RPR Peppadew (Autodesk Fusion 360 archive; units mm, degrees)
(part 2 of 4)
extrude "Extrude135" cut of existing geometry blind -3
extrude "Extrude136" cut of existing geometry blind -3
extrude "Extrude137" add of existing geometry blind 14
sketch "Sketch111" plane through (0, 0, 5) normal (0, 0, 1) x axis (1, 0, 0)
  line L1 (18.7, -99.4015) -> (49, -99.4015)
  line L2 (18.7, -90.8015) -> (18.7, -99.4015)
  line L3 (9, -90.8015) -> (18.7, -90.8015)
  line L4 (6.05, -90.8015) -> (9, -90.8015)
  line L5 (6.05, -100.6015) -> (6.05, -90.8015)
  line L6 (3, -100.6015) -> (6.05, -100.6015)
  line L7 (3, -101.4015) -> (3, -100.6015)
  line L8 (49, -101.4015) -> (3, -101.4015)
  line L9 (49, -99.4015) -> (49, -101.4015)
extrude "Extrude7" cut sketch "Sketch111" along normal blind 14
extrude "Extrude138" add of existing geometry blind 14
sketch "Sketch112" plane through (0, 0, 19) normal (0, 0, 1) x axis (1, 0, 0)
  line L1 (18.7, -99.4015) -> (49, -99.4015)
  line L2 (18.7, -90.8015) -> (18.7, -99.4015)
  line L3 (6.05, -90.8015) -> (18.7, -90.8015)
  line L4 (6.05, -100.6015) -> (6.05, -90.8015)
  line L5 (3, -100.6015) -> (6.05, -100.6015)
  line L6 (3, -101.4015) -> (3, -100.6015)
  line L7 (49, -101.4015) -> (3, -101.4015)
  line L8 (49, -99.4015) -> (49, -101.4015)
  line L9 (6.7, -33.0015) -> (6.7, -39.8015)
  line L10 (-9, -33.0015) -> (6.7, -33.0015)
  line L11 (-9, -12.8015) -> (-9, -33.0015)
  line L12 (-6.05, -12.8015) -> (-9, -12.8015)
  line L13 (-6.05, -3.0015) -> (-6.05, -12.8015)
  line L14 (-3, -3.0015) -> (-6.05, -3.0015)
  line L15 (-3, -2.2015) -> (-3, -3.0015)
  line L16 (-13.7, -2.2015) -> (-3, -2.2015)
  line L17 (-13.7, -39.8015) -> (-13.7, -2.2015)
  line L18 (6.7, -39.8015) -> (-13.7, -39.8015)
  line L19 (9, -4.2015) -> (9, -12.8015)
  line L20 (49, -4.2015) -> (9, -4.2015)
  line L21 (49, -2.2015) -> (49, -4.2015)
  line L22 (3, -2.2015) -> (49, -2.2015)
  line L23 (3, -3.0015) -> (3, -2.2015)
  line L24 (6.05, -3.0015) -> (3, -3.0015)
  line L25 (6.05, -12.8015) -> (6.05, -3.0015)
  line L26 (9, -12.8015) -> (6.05, -12.8015)
  line L27 (-6.05, -3.0015) -> (6.05, -3.0015)
  line L28 (-6.05, -2.2015) -> (-6.05, -3.0015)
  line L29 (6.05, -2.2015) -> (-6.05, -2.2015)
  line L30 (6.05, -3.0015) -> (6.05, -2.2015)
  line L31 (-13.7, -101.4015) -> (-13.7, -73.6015)
  line L32 (-3, -101.4015) -> (-13.7, -101.4015)
  line L33 (-3, -100.6015) -> (-3, -101.4015)
  line L34 (-6.05, -100.6015) -> (-3, -100.6015)
  line L35 (-6.05, -90.8015) -> (-6.05, -100.6015)
  line L36 (-9, -90.8015) -> (-6.05, -90.8015)
  line L37 (-9, -73.6015) -> (-9, -90.8015)
  line L38 (-13.7, -73.6015) -> (-9, -73.6015)
  line L39 (6.05, -100.6015) -> (-6.05, -100.6015)
  line L40 (6.05, -101.4015) -> (6.05, -100.6015)
  line L41 (-6.05, -101.4015) -> (6.05, -101.4015)
  line L42 (-6.05, -100.6015) -> (-6.05, -101.4015)
  point P30 (-6.05, -2.2015)
  point P26 (6.05, -3.0015)
  point P28 (6.05, -3.0015)
  point P42 (6.05, -101.4015)
  point P36 (-6.05, -100.6015)
  point P40 (-6.05, -100.6015)
  horizontal L27
  vertical L28
  horizontal L29
  vertical L30
  coincident L16 P30
  coincident P26 P28
  horizontal L39
  vertical L40
  horizontal L41
  vertical L42
  coincident L7 P42
  coincident P36 P40
extrude "Extrude139" cut sketch "Sketch112" profile of L5 L6 L7 L14 L15 L16 L22 L23 L24 L27 L28 L29 L30 L32 L33 L34 L39 L40 L41 L42 against normal blind 14.05
chamfer "Chamfer9" distance 8
sketch "Sketch113" plane through (0, -2.2015, 0) normal (0, 1, 0) x axis (-1, 0, 0)
  line L1 (13.7, -5) -> (5.7, -13)
  line L2 (13.7, 19) -> (13.7, -5)
  line L3 (6.05, 19) -> (13.7, 19)
  line L4 (6.05, 4.95) -> (6.05, 19)
  line L5 (3, 4.95) -> (6.05, 4.95)
  line L6 (3, 0) -> (3, 4.95)
  line L7 (-3, 4.95) -> (-3, 0)
  line L8 (-6.05, 4.95) -> (-3, 4.95)
  line L9 (-6.05, 19) -> (-6.05, 4.95)
  line L10 (-49, 19) -> (-6.05, 19)
  line L11 (-49, -13) -> (-49, 19)
  line L12 (5.7, -13) -> (-49, -13)
  line L13 (-106.3, -13) -> (13.7, 19)
  line L14 (8.7, -13) -> (-21.65, -13)
  line L15 (-106.3, -13) -> (8.7, -13)
  line L16 (-106.3, 70) -> (-106.3, -13)
  line L17 (13.7, 70) -> (-106.3, 70)
  line L18 (13.7, 19) -> (13.7, 70)
  arc A1 centre (0, 0) radius 3 clockwise from (3, 0) to (-3, 0)
  point P4 (13.7, 19)
  point P16 (13.7, 19)
  point P17 (-21.65, -13)
  point P18 (8.7, -13)
  point P19 (-106.3, -13)
  coincident P4 P16
  midpoint L12 P17
  coincident L12 P18
  parallel L12 L14
  parallel L12 L15
  perpendicular L15 L16
  perpendicular L2 L17
  perpendicular L3 L18
  dimension "d696" distance L2 P19 = 120
extrude "Extrude140" add of existing geometry blind 20
extrude "Extrude141" cut sketch "Sketch113" profile of L3 L4 L9 L10 L11 L13 L16 L17 L18 against normal blind 30.8
sketch "Sketch114" plane through (0, -101.4015, 0) normal (0, -1, 0) x axis (1, 0, 0)
  line L1 (-5.7, -13) -> (-13.7, -5)
  line L2 (69, -13) -> (-5.7, -13)
  line L3 (69, 19) -> (69, -13)
  line L4 (6.05, 19) -> (69, 19)
  line L5 (6.05, 4.95) -> (6.05, 19)
  line L6 (3, 4.95) -> (6.05, 4.95)
  line L7 (3, 0) -> (3, 4.95)
  line L8 (-3, 4.95) -> (-3, 0)
  line L9 (-6.05, 4.95) -> (-3, 4.95)
  line L10 (-6.05, 19) -> (-6.05, 4.95)
  line L11 (-13.7, 19) -> (-6.05, 19)
  line L12 (-13.7, -5) -> (-13.7, 19)
  line L13 (69, -3.0533) -> (6.05, 13.7333)
  line L14 (69, -13) -> (69, -3.0533)
  line L15 (-5.7, -13) -> (69, -13)
  line L16 (-13.7, -5) -> (-5.7, -13)
  line L17 (-13.7, 19) -> (-13.7, -5)
  line L18 (-6.05, 16.96) -> (-13.7, 19)
  line L19 (-6.05, 4.95) -> (-6.05, 16.96)
  line L20 (-3, 4.95) -> (-6.05, 4.95)
  line L21 (-3, 0) -> (-3, 4.95)
  line L22 (3, 4.95) -> (3, 0)
  line L23 (6.05, 4.95) -> (3, 4.95)
  line L24 (6.05, 13.7333) -> (6.05, 4.95)
  arc A1 centre (0, 0) radius 3 clockwise from (3, 0) to (-3, 0)
  arc A2 centre (0, 0) radius 3 clockwise from (3, 0) to (-3, 0)
extrude "Extrude142" cut sketch "Sketch114" profile of L3 L4 L5 L10 L11 L13 L18 against normal blind 10.6
component_insert "Component Insert8"
as_built_joint "As-built7"
joint "Assemble6" alignAngle 0 alignOffsetX -7 alignOffsetY 50 alignOffsetZ 0
extrude "Extrude143" add of existing geometry blind 3
sketch "Sketch115" plane through (0, -33.0015, 0) normal (0, 1, 0) x axis (-1, 0, 0)
  line L1 (-14.2, -11) -> (-14.2, 11.5)
  line L2 (-9, -11) -> (-14.2, -11)
  line L3 (-9, -2.3714) -> (-9, -11)
  line L4 (-6.9285, -2.3714) -> (-9, -2.3714)
  line L5 (-5.6202, -2.3714) -> (-6.9285, -2.3714)
  line L6 (3, -5.1) -> (-3, -5.1)
  line L7 (6.9285, -2.3714) -> (5.6202, -2.3714)
  line L8 (9, -2.3714) -> (6.9285, -2.3714)
  line L9 (9, 17.7467) -> (9, -2.3714)
  line L10 (13.7, 19) -> (9, 17.7467)
  line L11 (-6.7, 19) -> (13.7, 19)
  line L12 (-69, -3.0533) -> (-6.05, 13.7333)
  line L13 (-69, -13) -> (-69, -3.0533)
  line L14 (5.7, -13) -> (-69, -13)
  line L15 (13.7, -5) -> (5.7, -13)
  line L16 (13.7, 19) -> (13.7, -5)
  line L17 (6.05, 16.96) -> (13.7, 19)
  line L18 (6.05, 4.95) -> (6.05, 16.96)
  line L19 (3, 4.95) -> (6.05, 4.95)
  line L20 (3, 0) -> (3, 4.95)
  line L21 (-3, 4.95) -> (-3, 0)
  line L22 (-6.05, 4.95) -> (-3, 4.95)
  line L23 (-6.05, 13.7333) -> (-6.05, 4.95)
  line L24 (-69, -11.0004) -> (-9, -11.0004)
  line L25 (-9, -11.0004) -> (-69, -11.0004)
  arc A1 centre (0, 0) radius 6.1 clockwise from (-3.66, -4.88) to (-5.6202, -2.3714)
  arc A2 centre (-3, -4) radius 1.1 clockwise from (-3, -5.1) to (-3.66, -4.88)
  arc A3 centre (3, -4) radius 1.1 clockwise from (3.66, -4.88) to (3, -5.1)
  arc A4 centre (0, 0) radius 6.1 clockwise from (5.6202, -2.3714) to (3.66, -4.88)
  arc A5 centre (-6.7, 11.5) radius 7.5 clockwise from (-14.2, 11.5) to (-6.7, 19)
  circle C1 centre (-7.95, 12.8) radius 1.25
  arc A6 centre (0, 0) radius 3 clockwise from (3, 0) to (-3, 0)
extrude "Extrude144" add sketch "Sketch115" profile of L1 L2 L3 L4 L5 A1 A2 L6 A3 A4 L7 L8 L9 L10 L12 L13 L14 L15 L16 L17 against normal blind 5
sketch "Sketch116" plane through (0, -33.0015, 0) normal (0, 1, 0) x axis (-1, 0, 0)
  line L1 (-69, -3.0533) -> (-14.1998, 11.5601)
  line L2 (-69, -11.0004) -> (-69, -3.0533)
  line L3 (-9, -11.0004) -> (-69, -11.0004)
  line L4 (-9, -2.3714) -> (-9, -11.0004)
  line L5 (-6.9285, -2.3714) -> (-9, -2.3714)
  line L6 (-5.6202, -2.3714) -> (-6.9285, -2.3714)
  line L7 (3, -5.1) -> (-3, -5.1)
  line L8 (6.9285, -2.3714) -> (5.6202, -2.3714)
  line L9 (9, -2.3714) -> (6.9285, -2.3714)
  line L10 (9, 17.7467) -> (9, -2.3714)
  line L11 (13.7, 19) -> (9, 17.7467)
  line L12 (-6.7, 19) -> (13.7, 19)
  line L13 (-20.1998, -11.0004) -> (-69, -11.0004)
  line L14 (-20.1998, 9.9601) -> (-20.1998, -11.0004)
  line L15 (-69, 9.9601) -> (-20.1998, 9.9601)
  line L16 (-69, -11.0004) -> (-69, 9.9601)
  arc A1 centre (0, 0) radius 6.1 clockwise from (-3.66, -4.88) to (-5.6202, -2.3714)
  arc A2 centre (-3, -4) radius 1.1 clockwise from (-3, -5.1) to (-3.66, -4.88)
  arc A3 centre (3, -4) radius 1.1 clockwise from (3.66, -4.88) to (3, -5.1)
  arc A4 centre (0, 0) radius 6.1 clockwise from (5.6202, -2.3714) to (3.66, -4.88)
  arc A5 centre (-6.7, 11.5) radius 7.5 clockwise from (-14.1998, 11.5601) to (-6.7, 19)
  circle C1 centre (-7.95, 12.8) radius 1.25
  point P27 (-20.1998, 9.9601)
  point P4 (-69, -11.0004)
  point P25 (-69, -11.0004)
  point P2 (-14.1998, 11.5601)
  horizontal L13
  vertical L14
  horizontal L15
  vertical L16
  coincident L1 P27
  coincident P4 P25
  dimension "d711" distance P2 L14 = 6
extrude "Extrude145" cut sketch "Sketch116" profile of L1 L2 L3 L13 L14 L16 against normal blind 5
sketch "Sketch117" plane through (0, -4.2015, 0) normal (0, -1, 0) x axis (1, 0, 0)
  line L1 (9, 12.9467) -> (69, -3.0533)
  line L2 (9, -11.0004) -> (9, 12.9467)
  line L3 (69, -11.0004) -> (9, -11.0004)
  line L4 (69, -3.0533) -> (69, -11.0004)
  line L5 (20.1998, 9.9601) -> (20.1998, -11.0004)
  line L6 (14.1998, 11.5601) -> (20.1998, 9.9601)
  line L7 (14.2, -11) -> (14.2, 11.5)
  line L8 (9, -11) -> (14.2, -11)
  line L9 (9, -11.0004) -> (9, -11)
  line L10 (20.1998, -11.0004) -> (9, -11.0004)
  arc A1 centre (6.7, 11.5) radius 7.5 clockwise from (14.1998, 11.5601) to (14.2, 11.5)
extrude "Extrude146" add sketch "Sketch117" profile of L1 L2 L3 L5 L6 L7 L8 L9 L10 along normal blind 4
sketch "Sketch118" plane through (0, -99.4015, 0) normal (0, 1, 0) x axis (-1, 0, 0)
  line L1 (-69, -3.0533) -> (-18.7, 10.36)
  line L2 (-69, -11) -> (-69, -3.0533)
  line L3 (-18.7, -11) -> (-69, -11)
  line L4 (-18.7, 10.36) -> (-18.7, -11)
  line L5 (-24.7, 10.36) -> (-24.7, -11)
  dimension "d716" = -6
extrude "Extrude147" add sketch "Sketch118" profile of L1 L3 L4 L5 along normal blind 4
sketch "Sketch119" plane through (0, -71.2015, 0) normal (0, 1, 0) x axis (-1, 0, 0)
  line L1 (-13.7, 6.6) -> (-13.7, -11)
  line L2 (-18.7, 6.6) -> (-13.7, 6.6)
  line L3 (-18.7, -11) -> (-18.7, 6.6)
  line L4 (-13.7, -11) -> (-18.7, -11)
  line L5 (-18.7, 10.36) -> (-18.7, -11)
  line L6 (-24.7, 8.76) -> (-18.7, 10.36)
  line L7 (-24.7, -11) -> (-24.7, 8.76)
  line L8 (-18.7, -11) -> (-24.7, -11)
extrude "Extrude10" new body sketch "Sketch119" profile of L3 L5 L6 L7 L8 along normal blind 6
extrude "Extrude148" add of existing geometry blind 5
sketch "Sketch120" plane through (18.7, 0, 0) normal (-1, 0, 0) x axis (0, 0, 1)
  line L1 (10.36, -71.2015) -> (-11, -71.2015)
  line L2 (10.36, -65.2015) -> (10.36, -71.2015)
  line L3 (-11, -65.2015) -> (10.36, -65.2015)
  line L4 (-11, -71.2015) -> (-11, -65.2015)
  line L5 (19, -2.2015) -> (19, -33.0015)
  line L6 (-5, -2.2015) -> (19, -2.2015)
  line L7 (-5, -101.4015) -> (-5, -2.2015)
  line L8 (19, -101.4015) -> (-5, -101.4015)
  line L9 (19, -90.8015) -> (19, -101.4015)
  line L10 (19, -73.6015) -> (19, -90.8015)
  line L11 (6.6, -73.6015) -> (19, -73.6015)
  line L12 (6.6, -39.8015) -> (6.6, -73.6015)
  line L13 (19, -39.8015) -> (6.6, -39.8015)
  line L14 (19, -33.0015) -> (19, -39.8015)
extrude "Extrude11" add of existing geometry blind 12.4
extrude "Extrude12" cut of existing geometry blind -8.4
extrude "Extrude149" cut of existing geometry blind -6.8
sketch "Sketch121" plane through (0, 0, 6.6) normal (0, 0, 1) x axis (1, 0, 0)
  line L1 (-13.7, -39.8015) -> (-9, -39.8015)
  line L2 (-13.7, -73.6015) -> (-13.7, -39.8015)
  line L3 (-9, -73.6015) -> (-13.7, -73.6015)
  line L4 (-9, -39.8015) -> (-9, -73.6015)
  line L5 (-9, -39.8015) -> (-13.7, -39.8015)
  line L6 (-9, -63.8015) -> (-9, -39.8015)
  line L7 (-13.7, -63.8015) -> (-9, -63.8015)
  line L8 (-13.7, -39.8015) -> (-13.7, -63.8015)
  line L9 (-6.05, -2.2015) -> (-6.05, -12.8015)
  line L10 (-13.7, -2.2015) -> (-6.05, -2.2015)
  line L11 (-13.7, -33.0015) -> (-13.7, -2.2015)
  line L12 (-9, -33.0015) -> (-13.7, -33.0015)
  line L13 (-9, -12.8015) -> (-9, -33.0015)
  line L14 (-6.05, -12.8015) -> (-9, -12.8015)
  line L15 (-6.05, -101.4015) -> (-13.7, -101.4015)
  line L16 (-6.05, -90.8015) -> (-6.05, -101.4015)
  line L17 (-9, -90.8015) -> (-6.05, -90.8015)
  line L18 (-13.7, -90.8015) -> (-9, -90.8015)
  line L19 (-13.7, -101.4015) -> (-13.7, -90.8015)
  point P8 (-9, -63.8015)
  point P3 (-13.7, -39.8015)
  point P6 (-13.7, -39.8015)
  point P16 (-13.7, -101.4015)
  horizontal L5
  vertical L6
  horizontal L7
  vertical L8
  coincident L4 P8
  coincident P3 P6
  dimension "d729" distance L5 L10 = 37.6
  dimension "d730" distance L7 P16 = 37.6 (= "d729")
extrude "Extrude150" cut sketch "Sketch121" profile of L1 L2 L4 L5 L6 L7 L8 against normal blind 8.971
sketch "Sketch122" plane through (0, -99.4015, 0) normal (0, 1, 0) x axis (-1, 0, 0)
  line L1 (-24.7, 8.76) -> (-24.7, -11)
  line L2 (-69, -3.0533) -> (-24.7, 8.76)
  line L3 (-69, -11) -> (-69, -3.0533)
  line L4 (-24.7, -11) -> (-69, -11)
  line L5 (-6.05, 13.7333) -> (-69, -3.0533)
  line L6 (-6.05, 4.95) -> (-6.05, 13.7333)
  line L7 (-3, 4.95) -> (-6.05, 4.95)
  line L8 (-3, 0) -> (-3, 4.95)
  line L9 (3, 4.95) -> (3, 0)
  line L10 (6.05, 4.95) -> (3, 4.95)
  line L11 (6.05, 16.96) -> (6.05, 4.95)
  line L12 (13.7, 19) -> (6.05, 16.96)
  line L13 (13.7, -5) -> (13.7, 19)
  line L14 (5.7, -13) -> (13.7, -5)
  line L15 (-69, -13) -> (5.7, -13)
  line L16 (-69, -3.0533) -> (-69, -13)
  line L17 (-67, -13) -> (-69, -13)
  line L18 (-67, 2) -> (-67, -13)
  line L19 (-69, 2) -> (-67, 2)
  line L20 (-69, -13) -> (-69, 2)
  arc A1 centre (0, 0) radius 3 clockwise from (3, 0) to (-3, 0)
  point P19 (-69, -13)
  point P20 (-69, -13)
  point P21 (-67, -13)
  horizontal L17
  vertical L18
  horizontal L19
  vertical L20
  coincident P19 P20
  dimension "d733" distance P20 P21 = 2
extrude "Extrude151" add sketch "Sketch122" profile of L2 L3 L4 L5 L15 L16 L17 L18 L20 along normal blind 95.2
sketch "Sketch123" plane through (18.7, 0, 0) normal (1, 0, 0) x axis (0, 0, -1)
  line L1 (-19, -73.6015) -> (11, -73.6015)
  line L2 (-19, -83.6015) -> (-19, -73.6015)
  line L3 (-6.6, -83.6015) -> (-19, -83.6015)
  line L4 (-6.6, -90.8015) -> (-6.6, -83.6015)
  line L5 (-10.36, -90.8015) -> (-6.6, -90.8015)
  line L6 (-10.36, -95.4015) -> (-10.36, -90.8015)
  line L7 (11, -95.4015) -> (-10.36, -95.4015)
  line L8 (11, -73.6015) -> (11, -95.4015)
sketch "Sketch124" plane through (0, 0, -2.3714) normal (0, 0, 1) x axis (1, 0, 0)
  line L1 (-9, -39.8015) -> (-6.9285, -39.8015)
  line L2 (-9, -71.8015) -> (-9, -39.8015)
  line L3 (-6.9285, -71.8015) -> (-9, -71.8015)
  line L4 (-6.9285, -39.8015) -> (-6.9285, -71.8015)
  line L5 (19, -39.8015) -> (-9, -39.8015)
  line L6 (19, -72) -> (19, -39.8015)
  line L7 (-9, -72) -> (19, -72)
  line L8 (-9, -39.8015) -> (-9, -72)
  point P3 (-9, -39.8015)
  point P6 (-9, -39.8015)
  horizontal L5
  vertical L6
  horizontal L7
  vertical L8
  coincident P3 P6
extrude "Extrude152" cut sketch "Sketch124" against normal blind 8.629
sketch "Sketch125" plane through (0, -39.8015, 0) normal (0, -1, 0) x axis (1, 0, 0)
  line L1 (14.2, -11) -> (9, -11)
  line L2 (14.2, 11.5) -> (14.2, -11)
  line L3 (-13.7, 19) -> (6.7, 19)
  line L4 (-13.7, -2.371) -> (-13.7, 19)
  line L5 (-9, -2.371) -> (-13.7, -2.371)
  line L6 (-9, -2.3714) -> (-9, -2.371)
  line L7 (-9, -9.7) -> (-9, -2.3714)
  line L8 (-7.6996, -11.0004) -> (-9, -9.7)
  line L9 (9, -11.0004) -> (-7.6996, -11.0004)
  line L10 (9, -11) -> (9, -11.0004)
  line L11 (-4.8712, -11.0004) -> (-9.0004, -6.8712)
  arc A1 centre (6.7, 11.5) radius 7.5 clockwise from (6.7, 19) to (14.2, 11.5)
  circle C1 centre (7.95, 12.8) radius 1.25
  point P16 (-4.8712, -11.0004)
  coincident L9 P16
extrude "Extrude153" add sketch "Sketch125" profile of L7 L8 L9 L11 along normal blind 32.199
extrude "Extrude154" cut of existing geometry blind -1.601
sketch "Sketch127" plane through (0, -4.2015, 0) normal (0, -1, 0) x axis (1, 0, 0)
  line L1 (67, -2.52) -> (67, -11.0004)
  line L2 (20.1998, 9.9601) -> (67, -2.52)
  line L3 (20.1998, -11.0004) -> (20.1998, 9.9601)
  line L4 (67, -11.0004) -> (20.1998, -11.0004)
  circle C1 centre (25.1998, -3.5004) radius 8
  circle C2 centre (25.1998, -3.5004) radius 10.5
  point P6 (25.1998, -3.5004)
  point P7 (25.1998, -3.5004)
  concentric C1 C2
  dimension "d750" diameter C1 = 16
  dimension "d751" diameter C2 = 21
  dimension "d752" distance L4 P6 = 7.5
  dimension "d753" distance L3 P7 = 5
extrude "Extrude156" cut sketch "Sketch127" profile of L2 L3 L4 C1 C2 along normal blind 10.5 and along normal blind 7
work_plane "WorkPlane5" AlongDistance 14
sketch "Sketch128" plane through (25.1998, -25.2015, -12.0002) normal (0, -1, 0) x axis (-1, 0, 0)
  line L1 (7.3485, -0.9998) -> (2.7839, -0.9998)
  line L2 (-4.473, 0.9998) -> (4.473, 0.9998)
  line L3 (-2.7839, -0.9998) -> (-7.3485, -0.9998)
  arc A1 centre (0, -8.4998) radius 10.5 clockwise from (4.473, 0.9998) to (7.3485, -0.9998)
  arc A2 centre (0, -8.4998) radius 10.5 clockwise from (-7.3485, -0.9998) to (-4.473, 0.9998)
  arc A3 centre (0, -8.4998) radius 8 clockwise from (-2.7839, -0.9998) to (2.7839, -0.9998)
extrude "Extrude157" cut sketch "Sketch128" along normal blind 3.5
extrude "Extrude158" cut of existing geometry blind -10
sketch "Sketch129" plane through (0, -4.2015, 0) normal (0, -1, 0) x axis (1, 0, 0)
  line L1 (9, 12.9467) -> (14.1998, 11.5601)
  line L2 (9, -11) -> (9, 12.9467)
  line L3 (20.1998, -11) -> (9, -11)
  line L4 (20.1998, -11.0004) -> (20.1998, -11)
  line L5 (67, -11.0004) -> (20.1998, -11.0004)
  line L6 (67, -2.52) -> (67, -11.0004)
  line L7 (17.8513, -11.0004) -> (22.4159, -11.0004)
  line L8 (29.6727, -13) -> (20.7268, -13)
  line L9 (27.9836, -11.0004) -> (32.5482, -11.0004)
  line L10 (37.1998, -9) -> (13.1998, -9)
  line L11 (37.1998, -11.0004) -> (37.1998, -9)
  line L12 (13.1998, -11.0004) -> (37.1998, -11.0004)
  line L13 (13.1998, -9) -> (13.1998, -11.0004)
  line L14 (27.9836, -11.0004) -> (32.5482, -11.0004)
  line L15 (32.5482, -11.0004) -> (27.9836, -11.0004)
  line L16 (22.4159, -11.0004) -> (17.8513, -11.0004)
  line L17 (17.8513, -11.0004) -> (22.4159, -11.0004)
  line L18 (22.4159, -11.0004) -> (17.8513, -11.0004)
  line L19 (17.8513, -11.0004) -> (22.4159, -11.0004)
  line L20 (32.5482, -11.0004) -> (27.9836, -11.0004)
  line L21 (27.9836, -11.0004) -> (32.5482, -11.0004)
  line L22 (67, -11.0004) -> (19, -11.0004)
  line L23 (20.1998, -11.0004) -> (67, -11.0004)
  line L24 (9, -11.0004) -> (20.1998, -11.0004)
  line L25 (20.1998, -11.0004) -> (9, -11.0004)
  line L26 (9, -11.0004) -> (20.1998, -11.0004)
  line L27 (19, -11.0004) -> (9, -11.0004)
  line L28 (14.2, 11.5) -> (14.425, 11.5)
  line L29 (14.425, 11.5) -> (67, -2.52)
  arc A1 centre (25.1998, -3.5004) radius 10.5 clockwise from (20.7268, -13) to (17.8513, -11.0004)
  arc A2 centre (25.1998, -3.5004) radius 10.5 clockwise from (32.5482, -11.0004) to (29.6727, -13)
  arc A3 centre (25.1998, -3.5004) radius 8 clockwise from (27.9836, -11.0004) to (22.4159, -11.0004)
  circle C1 centre (25.1998, -3.5004) radius 8
  circle C2 centre (25.1998, -3.5004) radius 10.5
  arc A4 centre (6.7, 11.5) radius 7.5 clockwise from (14.1998, 11.5601) to (14.2, 11.5)
  point P14 (27.9836, -11.0004)
  point P13 (32.5482, -11.0004)
  point P19 (37.1998, -11.0004)
  point P16 (25.1998, -3.5004)
  point P17 (13.1998, -9)
  concentric A1 C1
  coincident P14 C1
  concentric C1 C2
  coincident P13 C2
  horizontal L10
  vertical L11
  horizontal L12
  vertical L13
  coincident L5 P19
  dimension "d763" distance P16 L11 = 12
  dimension "d764" distance P16 P17 = 12
extrude "Extrude159" add sketch "Sketch129" profile of L3 L4 L5 L7 A1 L8 A2 L9 A3 C1 C2 L10 L11 L12 L13 L14 L15 L16 L17 L18 L19 L20 L21 L22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 along normal blind 7
sketch "Sketch130" plane through (0, -11.2015, 0) normal (0, -1, 0) x axis (1, 0, 0)
  line L1 (17.8513, -11.0004) -> (13.1998, -11.0004)
  line L2 (29.6727, -13) -> (20.7268, -13)
  line L3 (37.1998, -11.0004) -> (32.5482, -11.0004)
  line L4 (37.1998, -9) -> (37.1998, -11.0004)
  line L5 (31.0096, -9) -> (37.1998, -9)
  line L6 (13.1998, -11.0004) -> (13.1998, -9)
  line L7 (13.1998, -9) -> (19.3899, -9)
  arc A1 centre (25.1998, -3.5004) radius 10.5 clockwise from (20.7268, -13) to (17.8513, -11.0004)
  arc A2 centre (25.1998, -3.5004) radius 10.5 clockwise from (32.5482, -11.0004) to (29.6727, -13)
  arc A3 centre (25.1998, -3.5004) radius 8 clockwise from (31.0096, -9) to (27.9836, -11.0004)
  arc A4 centre (25.1998, -3.5004) radius 8 clockwise from (27.9836, -11.0004) to (22.4159, -11.0004)
  circle C1 centre (25.1998, -3.5004) radius 10.5
  arc A5 centre (25.1998, -3.5004) radius 8 clockwise from (22.4159, -11.0004) to (19.3899, -9)
  point P7 (32.5482, -11.0004)
  concentric A1 C1
  coincident P7 C1
extrude "Extrude160" add sketch "Sketch130" profile of L3 L4 L5 L6 C1 along normal blind 3.5
sketch "Sketch131" plane through (0, -11.2015, 0) normal (0, -1, 0) x axis (1, 0, 0)
  line L1 (29.6727, -13) -> (20.7268, -13)
  line L2 (31.0096, -9) -> (34.1443, -9)
  line L3 (16.2552, -9) -> (19.3899, -9)
  arc A1 centre (25.1998, -3.5004) radius 10.5 clockwise from (20.7268, -13) to (16.2552, -9)
  arc A2 centre (25.1998, -3.5004) radius 10.5 clockwise from (34.1443, -9) to (29.6727, -13)
  arc A3 centre (25.1998, -3.5004) radius 8 clockwise from (31.0096, -9) to (27.9836, -11.0004)
  arc A4 centre (25.1998, -3.5004) radius 8 clockwise from (27.9836, -11.0004) to (22.4159, -11.0004)
  arc A5 centre (25.1998, -3.5004) radius 8 clockwise from (22.4159, -11.0004) to (19.3899, -9)
sketch "Sketch132" plane through (0, -14.7015, 0) normal (0, -1, 0) x axis (1, 0, 0)
  line L1 (37.1998, -11.0004) -> (32.5482, -11.0004)
  line L2 (37.1998, -9) -> (37.1998, -11.0004)
  line L3 (34.1443, -9) -> (37.1998, -9)
  line L4 (29.6727, -13) -> (20.7268, -13)
  line L5 (31.0096, -9) -> (34.1443, -9)
  line L6 (13.1998, -11.0004) -> (13.1998, -9)
  line L7 (17.8513, -11.0004) -> (13.1998, -11.0004)
  line L8 (16.2552, -9) -> (19.3899, -9)
  line L9
  arc A1 centre (25.1998, -3.5004) radius 10.5 clockwise from (34.1443, -9) to (32.5482, -11.0004)
  arc A2 centre (25.1998, -3.5004) radius 10.5 clockwise from (20.7268, -13) to (16.2552, -9)
  arc A3 centre (25.1998, -3.5004) radius 10.5 clockwise from (34.1443, -9) to (29.6727, -13)
  arc A4 centre (25.1998, -3.5004) radius 8 clockwise from (31.0096, -9) to (27.9836, -11.0004)
  arc A5 centre (25.1998, -3.5004) radius 8 clockwise from (27.9836, -11.0004) to (22.4159, -11.0004)
  arc A6 centre (25.1998, -3.5004) radius 10.5 clockwise from (17.8513, -11.0004) to (16.2552, -9)
  arc A7 centre (25.1998, -3.5004) radius 8 clockwise from (22.4159, -11.0004) to (19.3899, -9)
extrude "Extrude161" add sketch "Sketch132" profile of L1 L2 L3 A1 A2 L4 A3 L5 A4 A5 L6 A6 along normal blind 10.5
sketch "Sketch133" plane through (0, -25.2015, 0) normal (0, -1, 0) x axis (1, 0, 0)
  line L1 (29.6727, -13) -> (20.7268, -13)
  line L2 (37.1998, -11.0004) -> (32.5482, -11.0004)
  line L3 (37.1998, -9) -> (37.1998, -11.0004)
  line L4 (31.0096, -9) -> (37.1998, -9)
  line L5 (13.1998, -11.0004) -> (13.1998, -9)
  line L6 (29.6727, -13) -> (20.7268, -13)
  line L7 (31.0096, -9) -> (34.1443, -9)
  line L8 (13.1998, -9) -> (19.3899, -9)
  line L9 (17.8513, -11.0004) -> (13.1998, -11.0004)
  line L10 (16.2552, -9) -> (19.3899, -9)
  arc A1 centre (25.1998, -3.5004) radius 10.5 clockwise from (20.7268, -13) to (17.8513, -11.0004)
  arc A2 centre (25.1998, -3.5004) radius 10.5 clockwise from (32.5482, -11.0004) to (29.6727, -13)
  arc A3 centre (25.1998, -3.5004) radius 8 clockwise from (31.0096, -9) to (27.9836, -11.0004)
  arc A4 centre (25.1998, -3.5004) radius 8 clockwise from (27.9836, -11.0004) to (22.4159, -11.0004)
  arc A5 centre (25.1998, -3.5004) radius 8 clockwise from (22.4159, -11.0004) to (19.3899, -9)
  arc A6 centre (25.1998, -3.5004) radius 10.5 clockwise from (20.7268, -13) to (16.2552, -9)
  arc A7 centre (25.1998, -3.5004) radius 10.5 clockwise from (34.1443, -9) to (29.6727, -13)
  arc A8 centre (25.1998, -3.5004) radius 8 clockwise from (31.0096, -9) to (27.9836, -11.0004)
  arc A9 centre (25.1998, -3.5004) radius 8 clockwise from (27.9836, -11.0004) to (22.4159, -11.0004)
  arc A10 centre (25.1998, -3.5004) radius 8 clockwise from (22.4159, -11.0004) to (19.3899, -9)
extrude "Extrude162" add sketch "Sketch133" profile of L2 L3 L4 L5 A6 A7 along normal blind 3.5
sketch "Sketch134" plane through (0, -28.7015, 0) normal (0, 1, 0) x axis (-1, 0, 0)
  line L1 (-22.4159, -11.0004) -> (-17.8513, -11.0004)
  line L2 (-32.5482, -11.0004) -> (-27.9836, -11.0004)
  line L3 (-20.7268, -13) -> (-29.6727, -13)
  line L4 (-37.1998, -11.0004) -> (-32.5482, -11.0004)
  line L5 (-37.1998, -9) -> (-37.1998, -11.0004)
  line L6 (-34.1443, -9) -> (-37.1998, -9)
  line L7 (-29.6727, -13) -> (-20.7268, -13)
  line L8 (-31.0096, -9) -> (-34.1443, -9)
  line L9 (-16.2552, -9) -> (-19.3899, -9)
  line L10 (-13.1998, -9) -> (-16.2552, -9)
  line L11 (-13.1998, -11.0004) -> (-13.1998, -9)
  line L12 (-17.8513, -11.0004) -> (-13.1998, -11.0004)
  arc A1 centre (-25.1998, -3.5004) radius 10.5 clockwise from (-17.8513, -11.0004) to (-20.7268, -13)
  arc A2 centre (-25.1998, -3.5004) radius 8 clockwise from (-22.4159, -11.0004) to (-27.9836, -11.0004)
  arc A3 centre (-25.1998, -3.5004) radius 10.5 clockwise from (-29.6727, -13) to (-32.5482, -11.0004)
  arc A4 centre (-25.1998, -3.5004) radius 10.5 clockwise from (-32.5482, -11.0004) to (-34.1443, -9)
  arc A5 centre (-25.1998, -3.5004) radius 10.5 clockwise from (-16.2552, -9) to (-20.7268, -13)
  arc A6 centre (-25.1998, -3.5004) radius 10.5 clockwise from (-29.6727, -13) to (-34.1443, -9)
  arc A7 centre (-25.1998, -3.5004) radius 8 clockwise from (-27.9836, -11.0004) to (-31.0096, -9)
  arc A8 centre (-25.1998, -3.5004) radius 8 clockwise from (-22.4159, -11.0004) to (-27.9836, -11.0004)
  arc A9 centre (-25.1998, -3.5004) radius 8 clockwise from (-19.3899, -9) to (-22.4159, -11.0004)
  arc A10 centre (-25.1998, -3.5004) radius 10.5 clockwise from (-16.2552, -9) to (-17.8513, -11.0004)
extrude "Extrude163" add sketch "Sketch134" profile of L1 L2 L4 L5 L6 A4 A5 A6 L8 A7 A9 L9 L10 L11 L12 A10 against normal blind 9.3
sketch "Sketch135" plane through (0, -38.0015, 0) normal (0, -1, 0) x axis (1, 0, 0)
  line L1 (14.2, -11) -> (14.2, 11.5)
  line L2 (9, -11) -> (14.2, -11)
  line L3 (9, -11.0004) -> (9, -11)
  line L4 (22.4159, -11.0004) -> (9, -11.0004)
  line L5 (20.1998, 9.9601) -> (20.1998, -9.7454)
  line L6 (14.1998, 11.5601) -> (20.1998, 9.9601)
  line L7 (31.0096, -9) -> (37.1998, -9)
  line L8 (37.1998, -11.0004) -> (27.9836, -11.0004)
  line L9 (37.1998, -9) -> (37.1998, -11.0004)
  line L10 (20.1998, 6.9601) -> (20.1998, 9.9601)
  line L11 (14.2, -5.0004) -> (20.1998, 6.9601)
  arc A1 centre (25.1998, -3.5004) radius 8 clockwise from (22.4159, -11.0004) to (20.1998, -9.7454)
  arc A2 centre (25.1998, -3.5004) radius 8
  circle C1 centre (25.1998, -3.5004) radius 8
  arc A3 centre (6.7, 11.5) radius 7.5 clockwise from (14.1998, 11.5601) to (14.2, 11.5)
  point P6 (22.4159, -11.0004)
  point P9 (20.1998, 9.9601)
  point P16 (20.1998, 9.9601)
  point P17 (20.1998, 6.9601)
  point P18 (14.2, -5.0004)
  concentric A2 C1
  coincident P6 C1
  coincident P9 P16
  coincident L5 P17
  parallel L5 L10
  coincident L1 P18
  dimension "d775" distance L4 P18 = 6
  dimension "d776" distance P16 P17 = 3
extrude "Extrude164" cut sketch "Sketch135" profile of L1 L2 L3 L4 A1 L5 C1 L11 against normal blind 5
extrude "Extrude165" add of existing geometry blind 5
chamfer "Chamfer10" distance 2
component_insert "Component Insert9"
joint "Assemble7" alignAngle -90 alignOffsetX -20 alignOffsetY -10 alignOffsetZ -5
sketch "Sketch136" plane through (0, -4.2015, 0) normal (0, -1, 0) x axis (1, 0, 0)
  line L1 (15.1998, -9) -> (13.1998, -11)
  line L2 (19.3899, -9) -> (15.1998, -9)
  line L3 (27.9836, -11.0004) -> (22.4159, -11.0004)
  line L4 (35.1998, -9) -> (31.0096, -9)
  line L5 (37.1998, -11) -> (35.1998, -9)
  line L6 (37.1998, -11.0004) -> (37.1998, -11)
  line L7 (67, -11.0004) -> (37.1998, -11.0004)
  line L8 (67, -2.52) -> (67, -11.0004)
  line L9 (14.425, 11.5) -> (67, -2.52)
  line L10 (14.2, 11.5) -> (14.425, 11.5)
  line L11 (9, 12.9467) -> (14.1998, 11.5601)
  line L12 (9, -11) -> (9, 12.9467)
  line L13 (13.1998, -11) -> (9, -11)
  arc A1 centre (25.1998, -3.5004) radius 8 clockwise from (22.4159, -11.0004) to (19.3899, -9)
  arc A2 centre (25.1998, -3.5004) radius 8 clockwise from (31.0096, -9) to (27.9836, -11.0004)
  arc A3 centre (6.7, 11.5) radius 7.5 clockwise from (14.1998, 11.5601) to (14.2, 11.5)
  arc A4 centre (25.1998, -3.5004) radius 8 clockwise from (31.0096, -9) to (27.9836, -11.0004)
  arc A5 centre (25.1998, -3.5004) radius 8 clockwise from (31.0096, -9) to (27.9836, -11.0004)
  circle C1 centre (25.1998, -3.5004) radius 8
  concentric A4 C1
  dimension "d786" diameter C1 = 16
extrude "Extrude13" new body sketch "Sketch136" profile of A1 L3 A2 A4 A5 C1 along normal blind 33.8
sketch "Sketch137" plane through (0, 0, -11.0004) normal (0, 0, 1) x axis (1, 0, 0)
  line L1 (22.4159, -38.0015) -> (22.4159, -28.7015)
  line L2 (13.1998, -38.0015) -> (22.4159, -38.0015)
  line L3 (13.1998, -8.2015) -> (13.1998, -38.0015)
  line L4 (9, -8.2015) -> (13.1998, -8.2015)
  line L5 (9, -39.8015) -> (9, -8.2015)
  line L6 (9, -71.8015) -> (9, -39.8015)
  line L7 (19, -71.8015) -> (9, -71.8015)
  line L8 (67, -71.8015) -> (19, -71.8015)
  line L9 (67, -4.2015) -> (67, -71.8015)
  line L10 (37.1998, -4.2015) -> (67, -4.2015)
  line L11 (37.1998, -38.0015) -> (37.1998, -4.2015)
  line L12 (27.9836, -38.0015) -> (37.1998, -38.0015)
  line L13 (27.9836, -28.7015) -> (27.9836, -38.0015)
  line L14 (27.9836, -25.2015) -> (27.9836, -28.7015)
  line L15 (27.9836, -14.7015) -> (27.9836, -25.2015)
  line L16 (27.9836, -11.2015) -> (27.9836, -14.7015)
  line L17 (27.9836, -4.2015) -> (27.9836, -11.2015)
  line L18 (22.4159, -4.2015) -> (27.9836, -4.2015)
  line L19 (22.4159, -11.2015) -> (22.4159, -4.2015)
  line L20 (22.4159, -14.7015) -> (22.4159, -11.2015)
  line L21 (22.4159, -25.2015) -> (22.4159, -14.7015)
  line L22 (22.4159, -28.7015) -> (22.4159, -25.2015)
  line L23 (61.5, -4.2015) -> (67, -4.2015)
  line L24 (61.5, -8.2015) -> (61.5, -4.2015)
  line L25 (67, -8.2015) -> (61.5, -8.2015)
  line L26 (67, -4.2015) -> (67, -8.2015)
  point P11 (67, -4.2015)
  point P24 (67, -4.2015)
  point P25 (61.5, -4.2015)
  point P27 (67, -8.2015)
  horizontal L23
  vertical L24
  horizontal L25
  vertical L26
  coincident P11 P24
  dimension "d789" distance P24 P25 = 5.5
  dimension "d790" distance P24 P27 = 4
extrude "Extrude166" add sketch "Sketch137" profile of L9 L10 L23 L24 L25 L26 along normal blind 15
extrude "Extrude167" cut of existing geometry blind -10
sketch "Sketch138" plane through (0, -4.2015, 0) normal (0, -1, 0) x axis (1, 0, 0)
  line L1 (61.5, -1.0533) -> (61.5, -11.0004)
  line L2 (14.425, 11.5) -> (61.5, -1.0533)
  line L3 (14.2, 11.5) -> (14.425, 11.5)
  line L4 (9, 12.9467) -> (14.1998, 11.5601)
  line L5 (9, -11) -> (9, 12.9467)
  line L6 (13.1998, -11) -> (9, -11)
  line L7 (15.1998, -9) -> (13.1998, -11)
  line L8 (19.3899, -9) -> (15.1998, -9)
  line L9 (27.9836, -11.0004) -> (22.4159, -11.0004)
  line L10 (35.1998, -9) -> (31.0096, -9)
  line L11 (37.1998, -11) -> (35.1998, -9)
  line L12 (37.1998, -11.0004) -> (37.1998, -11)
  line L13 (61.5, -11.0004) -> (37.1998, -11.0004)
  line L14 (60.4649, -5.952) -> (36.3091, 0.4895)
  line L15 (61.7532, -1.1209) -> (60.4649, -5.952)
  line L16 (37.5974, 5.3207) -> (61.7532, -1.1209)
  line L17 (36.3091, 0.4895) -> (37.5974, 5.3207)
  line L18 (61.5, -5.952) -> (60.4649, -5.952)
  line L19 (36.3091, 0.4895) -> (60.4649, -5.952)
  line L20 (35.1998, -9) -> (36.3091, 0.4895)
  line L21 (35.7937, -1.4429) -> (59.9496, -7.8845)
  line L22 (59.9496, -11.0004) -> (59.9496, -7.8845)
  line L23 (59.5169, -7.7691) -> (59.9496, -7.8845)
  arc A1 centre (6.7, 11.5) radius 7.5 clockwise from (14.1998, 11.5601) to (14.2, 11.5)
  arc A2 centre (25.1998, -3.5004) radius 8 clockwise from (22.4159, -11.0004) to (19.3899, -9)
  arc A3 centre (25.1998, -3.5004) radius 8 clockwise from (31.0096, -9) to (27.9836, -11.0004)
  point P21 (60.4649, -5.952)
  point P24 (60.4649, -5.952)
  point P25 (61.5, -5.952)
  point P20 (36.3091, 0.4895)
  point P26 (36.3091, 0.4895)
  point P17 (35.1998, -9)
  point P27 (35.1998, -9)
  point P30 (59.9496, -11.0004)
  point P31 (59.5169, -7.7691)
  coincident P21 P24
  coincident L1 P25
  perpendicular L1 L18
  coincident P20 P26
  coincident P17 P27
  coincident L13 P30
  perpendicular L13 L22
  coincident L21 P31
  dimension "d796" = -2
extrude "Extrude168" add sketch "Sketch138" profile of L1 L11 L12 L13 L14 L18 L19 L20 L21 L22 L23 along normal blind 2
sketch "Sketch139" plane through (0.2577, -20.2015, 0.9662) normal (0, -1, 0) x axis (1, 0, 0)
  line L1 (60.2073, -6.9183) -> (36.0514, -0.4767)
  line L2 (61.4956, -2.0871) -> (60.2073, -6.9183)
  line L3 (37.3397, 4.3545) -> (61.4956, -2.0871)
  line L4 (36.0514, -0.4767) -> (37.3397, 4.3545)
  line L5 (36.0514, -0.4767) -> (60.2073, -6.9183)
  line L6 (34.9421, -9.9662) -> (36.0514, -0.4767)
  line L7 (36.9421, -11.9662) -> (34.9421, -9.9662)
  line L8 (36.9421, -11.9666) -> (36.9421, -11.9662)
  line L9 (61.2423, -11.9666) -> (36.9421, -11.9666)
  line L10 (61.2423, -6.9183) -> (61.2423, -11.9666)
  line L11 (60.2073, -6.9183) -> (61.2423, -6.9183)
extrude "Extrude169" add sketch "Sketch139" profile of L1 L5 L6 L7 L8 L9 L10 L11 against normal blind 2
sketch "Sketch140" plane through (0, -20.2015, 0) normal (0, -1, 0) x axis (1, 0, 0)
  line L1 (60.4649, -5.952) -> (61.5, -5.952)
  line L2 (36.3091, 0.4895) -> (60.4649, -5.952)
  line L3 (35.1998, -9) -> (36.3091, 0.4895)
  line L4 (37.1998, -11) -> (35.1998, -9)
  line L5 (37.1998, -11.0004) -> (37.1998, -11)
  line L6 (61.5, -11.0004) -> (37.1998, -11.0004)
  line L7 (61.5, -5.952) -> (61.5, -11.0004)
  line L8 (36.979, 3.0017) -> (66.9323, -4.9858)
  line L9 (61.5, 254.2187) -> (61.5, -11.0004)
  line L10 (36.3091, 0.4895) -> (36.979, 3.0017)
  point P8 (61.5, -11.0004)
  point P10 (61.5, -11.0004)
  point P4 (36.3091, 0.4895)
  point P13 (36.3091, 0.4895)
  coincident P8 P10
  coincident P4 P13
  perpendicular L2 L10
extrude "Extrude170" add sketch "Sketch140" along normal blind 2
sketch "Sketch141" plane through (0, -2.2015, 0) normal (0, 1, 0) x axis (-1, 0, 0)
  line L1 (-69, -3.0533) -> (-6.05, 13.7333)
  line L2 (-69, -13) -> (-69, -3.0533)
  line L3 (5.7, -13) -> (-69, -13)
  line L4 (13.7, -5) -> (5.7, -13)
  line L5 (13.7, 19) -> (13.7, -5)
  line L6 (6.05, 16.96) -> (13.7, 19)
  line L7 (6.05, 4.95) -> (6.05, 16.96)
  line L8 (3, 4.95) -> (6.05, 4.95)
  line L9 (3, 0) -> (3, 4.95)
  line L10 (-3, 4.95) -> (-3, 0)
  line L11 (-6.05, 4.95) -> (-3, 4.95)
  line L12 (-6.05, 13.7333) -> (-6.05, 4.95)
  arc A1 centre (0, 0) radius 3 clockwise from (3, 0) to (-3, 0)
  circle C1 centre (-57.6661, -0.031) radius 6.1767
  point P16 (-57.6661, -0.031)
  coincident L1 P16
extrude "Extrude171" cut sketch "Sketch141" profile of L1 C1 against normal blind 2
component_insert "Component Insert10"
as_built_joint "As-built8"
joint "Assemble8" alignAngle 90 alignOffsetX 5 alignOffsetY 5 alignOffsetZ 0
sketch "Sketch142" plane through (0, 0, -11) normal (0, 0, 1) x axis (1, 0, 0)
  line L1 (9, -73.601) -> (19, -73.601)
  line L2 (9, -73.6015) -> (9, -73.601)
  line L3 (18.7, -73.6015) -> (9, -73.6015)
  line L4 (18.7, -95.4015) -> (18.7, -73.6015)
  line L5 (24.7, -95.4015) -> (18.7, -95.4015)
  line L6 (24.7, -99.4015) -> (24.7, -95.4015)
  line L7 (67, -99.4015) -> (24.7, -99.4015)
  line L8 (67, -71.8015) -> (67, -99.4015)
  line L9 (19, -71.8015) -> (67, -71.8015)
  line L10 (19, -73.601) -> (19, -71.8015)
  line L11 (61.5, -99.4015) -> (67, -99.4015)
  line L12 (61.5, -95.4015) -> (61.5, -99.4015)
  line L13 (67, -95.4015) -> (61.5, -95.4015)
  line L14 (67, -99.4015) -> (67, -95.4015)
  point P9 (67, -99.4015)
  point P12 (67, -99.4015)
  point P13 (61.5, -99.4015)
  point P15 (67, -95.4015)
  horizontal L11
  vertical L12
  horizontal L13
  vertical L14
  coincident P9 P12
  dimension "d810" distance P12 P13 = 5.5
  dimension "d811" distance P12 P15 = 4
extrude "Extrude172" add sketch "Sketch142" profile of L7 L8 L11 L12 L13 L14 along normal blind 15
extrude "Extrude173" cut of existing geometry blind -17
sketch "Sketch143" plane through (3.8207, 0, 14.3278) normal (0.2577, 0, 0.9662) x axis (0.9662, 0, -0.2577)
  line L1 (-10.2157, -2.2015) -> (-10.2157, -12.8015)
  line L2 (-18.133, -2.2015) -> (-10.2157, -2.2015)
  line L3 (-18.133, -33.0015) -> (-18.133, -2.2015)
  line L4 (-13.2688, -33.0015) -> (-18.133, -33.0015)
  line L5 (-13.2688, -12.8015) -> (-13.2688, -33.0015)
  line L6 (-10.2157, -12.8015) -> (-13.2688, -12.8015)
  line L7 (-14.1743, -2.2015) -> (-18.133, -2.2015)
  line L8 (107.867, -2.2015) -> (-18.133, -2.2015)
  line L9 (107.867, -33.0015) -> (107.867, -2.2015)
  line L10 (-18.133, -33.0015) -> (107.867, -33.0015)
  line L11 (-18.133, -2.2015) -> (-18.133, -33.0015)
  line L12 (107.867, -33.0015) -> (10.7417, -33.0015)
  line L13 (107.867, -38.0015) -> (107.867, -33.0015)
  line L14 (10.7417, -38.0015) -> (107.867, -38.0015)
  line L15 (10.7417, -33.0015) -> (10.7417, -38.0015)
  line L16 (67.4569, -2.2015) -> (67.4569, -101.4015)
  circle C1 centre (64.4569, -5.2015) radius 3
  circle C2 centre (13.7417, -35.0015) radius 3
  circle C3 centre (-14.633, -5.7015) radius 3.5
  circle C4 centre (-14.633, -29.5015) radius 3.5
  circle C5 centre (-14.633, -5.7015) radius 1.25
  circle C6 centre (-14.633, -29.5015) radius 1.25
  circle C7 centre (64.4569, -5.2015) radius 1.25
  circle C8 centre (13.7417, -35.0015) radius 1.25
  point P4 (-18.133, -2.2015)
  point P8 (-18.133, -2.2015)
  point P9 (-14.1743, -2.2015)
  point P12 (-18.133, -33.0015)
  point P13 (10.7417, -33.0015)
  point P15 (10.7417, -38.0015)
  point P16 (10.7417, -38.0015)
  point P10 (107.867, -2.2015)
  coincident P4 P8
  midpoint L2 P9
  horizontal L8
  vertical L9
  horizontal L10
  vertical L11
  coincident L4 P12
  horizontal L12
  vertical L13
  horizontal L14
  vertical L15
  coincident L10 P13
  coincident P15 P16
  concentric C3 C5
  concentric C4 C6
  concentric C1 C7
  concentric C2 C8
  tangent L10 C4
  tangent L11 C4
  tangent L11 C3
  tangent L7 C3
  tangent C1 L16
  tangent L8 C1
  tangent L14 C2
  tangent L15 C2
  dimension "d816" distance P8 P10 = 126
  dimension "d817" diameter C1 = 6
  dimension "d818" diameter C2 = 6
  dimension "d819" diameter C3 = 7
  dimension "d820" diameter C4 = 7
  dimension "d821" diameter C5 = 2.5
  dimension "d822" diameter C6 = 2.5
  dimension "d823" diameter C7 = 2.5
  dimension "d824" diameter C8 = 2.5
sketch "Sketch149" plane through (0, -2.2015, 0) normal (0, 1, 0) x axis (-1, 0, 0)
  line L1 (-69, -3.0533) -> (-63.6343, -1.6225)
  line L2 (-69, -13) -> (-69, -3.0533)
  line L3 (5.7, -13) -> (-69, -13)
  line L4 (13.7, -5) -> (5.7, -13)
  line L5 (13.7, 19) -> (13.7, -5)
  line L6 (6.05, 16.96) -> (13.7, 19)
  line L7 (6.05, 4.95) -> (6.05, 16.96)
  line L8 (3, 4.95) -> (6.05, 4.95)
  line L9 (3, 0) -> (3, 4.95)
  line L10 (-3, 4.95) -> (-3, 0)
  line L11 (-6.05, 4.95) -> (-3, 4.95)
  line L12 (-6.05, 13.7333) -> (-6.05, 4.95)
  line L13 (-51.698, 1.5605) -> (-6.05, 13.7333)
  line L14 (15.7, 11) -> (13.7, 19)
  line L15 (13.7, -5) -> (15.7, 11)
  arc A1 centre (-57.6661, -0.031) radius 6.1767 clockwise from (-51.698, 1.5605) to (-63.6343, -1.6225)
  arc A2 centre (0, 0) radius 3 clockwise from (3, 0) to (-3, 0)
  point P9 (13.7, 19)
  point P19 (13.7, 19)
  point P8 (13.7, -5)
  point P21 (13.7, -5)
  point P20 (15.7, 11)
  coincident P9 P19
  coincident P8 P21
  dimension "d846" distance P19 P20 = 2
  dimension "d847" distance P19 P20 = 8
extrude "Extrude178" add sketch "Sketch149" profile of L5 L14 L15 against normal blind 99.2
extrude "Extrude179" cut of existing geometry blind -17
extrude "Extrude174" cut sketch "Sketch143" profile of C5 C6 C7 C8 against normal blind 11
sketch "Sketch145" plane through (0, 0, -11.0004) normal (0, 0, 1) x axis (1, 0, 0)
  line L1 (37.1998, -22.2015) -> (61.5, -22.2015)
  line L2 (37.1998, -38.0015) -> (37.1998, -22.2015)
  line L3 (27.9836, -38.0015) -> (37.1998, -38.0015)
  line L4 (27.9836, -28.7015) -> (27.9836, -38.0015)
  line L5 (27.9836, -25.2015) -> (27.9836, -28.7015)
  line L6 (27.9836, -14.7015) -> (27.9836, -25.2015)
  line L7 (27.9836, -11.2015) -> (27.9836, -14.7015)
  line L8 (27.9836, -4.2015) -> (27.9836, -11.2015)
  line L9 (22.4159, -4.2015) -> (27.9836, -4.2015)
  line L10 (22.4159, -11.2015) -> (22.4159, -4.2015)
  line L11 (22.4159, -14.7015) -> (22.4159, -11.2015)
  line L12 (22.4159, -25.2015) -> (22.4159, -14.7015)
  line L13 (22.4159, -28.7015) -> (22.4159, -25.2015)
  line L14 (22.4159, -38.0015) -> (22.4159, -28.7015)
  line L15 (13.1998, -38.0015) -> (22.4159, -38.0015)
  line L16 (13.1998, -8.2015) -> (13.1998, -38.0015)
  line L17 (9, -8.2015) -> (13.1998, -8.2015)
  line L18 (9, -39.8015) -> (9, -8.2015)
  line L19 (9, -71.8015) -> (9, -39.8015)
  line L20 (19, -71.8015) -> (9, -71.8015)
  line L21 (67, -71.8015) -> (19, -71.8015)
  line L22 (67, -8.2015) -> (67, -71.8015)
  line L23 (61.5, -8.2015) -> (67, -8.2015)
  line L24 (61.5, -6.2015) -> (61.5, -8.2015)
  line L25 (37.1998, -6.2015) -> (61.5, -6.2015)
  line L26 (37.1998, -18.2015) -> (37.1998, -6.2015)
  line L27 (61.5, -18.2015) -> (37.1998, -18.2015)
  line L28 (61.5, -22.2015) -> (61.5, -18.2015)
  line L29 (14.1998, -38.0015) -> (108.0456, -38.0015)
  line L30 (61.5, -38.0015) -> (67, -38.0015)
  line L31 (61.5, -32.0015) -> (61.5, -38.0015)
  line L32 (67, -32.0015) -> (61.5, -32.0015)
  line L33 (67, -38.0015) -> (67, -32.0015)
  point P32 (67, -38.0015)
  point P33 (61.5, -38.0015)
  point P35 (67, -32.0015)
  horizontal L30
  vertical L31
  horizontal L32
  vertical L33
  coincident L29 P32
  coincident L22 P32
  dimension "d827" distance P32 P33 = 5.5
  dimension "d828" distance P32 P35 = 6
extrude "Extrude175" add sketch "Sketch145" profile of L22 L29 L30 L31 L32 L33 along normal blind 17
sketch "Sketch146" plane through (0, -32.0015, 0) normal (0, 1, 0) x axis (-1, 0, 0)
  line L1 (-61.5, -11.0004) -> (-67, -11.0004)
  line L2 (-61.5, 5.9996) -> (-61.5, -11.0004)
  line L3 (-67, 5.9996) -> (-61.5, 5.9996)
  line L4 (-67, -2.52) -> (-67, 5.9996)
  line L5 (-67, -11.0004) -> (-67, -2.52)
  line L6 (-69, -3.0533) -> (-63.6343, -1.6225)
  line L7 (-69, -13) -> (-69, -3.0533)
  line L8 (5.7, -13) -> (-69, -13)
  line L9 (13.7, -5) -> (5.7, -13)
  line L10 (6.05, 4.95) -> (6.05, 16.96)
  line L11 (3, 4.95) -> (6.05, 4.95)
  line L12 (3, 0) -> (3, 4.95)
  line L13 (-3, 4.95) -> (-3, 0)
  line L14 (-6.05, 4.95) -> (-3, 4.95)
  line L15 (-6.05, 13.7333) -> (-6.05, 4.95)
  line L16 (-51.698, 1.5605) -> (-6.05, 13.7333)
  line L17 (-60.638, -0.8235) -> (-67, -2.52)
  line L18 (15.7, 11) -> (13.7, -5)
  line L19 (13.7, 19) -> (15.7, 11)
  line L20 (6.05, 16.96) -> (13.7, 19)
  arc A1 centre (-57.6661, -0.031) radius 6.1767 clockwise from (-51.698, 1.5605) to (-63.6343, -1.6225)
  arc A2 centre (0, 0) radius 3 clockwise from (3, 0) to (-3, 0)
  point P6 (-67, -2.52)
  point P23 (-67, -2.52)
  coincident P6 P23
  parallel L6 L17
extrude "Extrude176" cut sketch "Sketch146" profile of L2 L3 L4 L6 L17 against normal blind 8
extrude "Extrude14" new body sketch "Sketch143" along normal blind 1
sketch "Sketch147" plane through (4.0784, 0, 15.294) normal (0.2577, 0, 0.9662) x axis (0.9662, 0, -0.2577)
  line L1 (107.867, -38.0015) -> (10.7417, -38.0015)
  line L2 (107.867, -2.2015) -> (107.867, -38.0015)
  line L3 (-18.133, -2.2015) -> (107.867, -2.2015)
  line L4 (-18.133, -33.0015) -> (-18.133, -2.2015)
  line L5 (10.7417, -33.0015) -> (-18.133, -33.0015)
  line L6 (10.7417, -38.0015) -> (10.7417, -33.0015)
  line L7 (61.9037, -4.2015) -> (61.9037, -2.2015)
  line L8 (59.6949, -4.2015) -> (61.9037, -4.2015)
  line L9 (59.6949, -8.2015) -> (59.6949, -4.2015)
  line L10 (65.3871, -8.2015) -> (59.6949, -8.2015)
  line L11 (65.3871, -32.0015) -> (65.3871, -8.2015)
  line L12 (59.6949, -32.0015) -> (65.3871, -32.0015)
  line L13 (59.6949, -38.0015) -> (59.6949, -32.0015)
  line L14 (65.3871, -95.4015) -> (65.3871, -38.0015)
  line L15 (59.6949, -95.4015) -> (65.3871, -95.4015)
  line L16 (59.6949, -99.4015) -> (59.6949, -95.4015)
  line L17 (21.6089, -99.4015) -> (59.6949, -99.4015)
  line L18 (21.6089, -95.4015) -> (21.6089, -99.4015)
  line L19 (15.3992, -95.4015) -> (21.6089, -95.4015)
  line L20 (15.3992, -90.8015) -> (15.3992, -95.4015)
  line L21 (2.3072, -90.8015) -> (15.3992, -90.8015)
  line L22 (2.3072, -101.4015) -> (2.3072, -90.8015)
  line L23 (67.4569, -101.4015) -> (2.3072, -101.4015)
  line L24 (67.4569, -2.2015) -> (67.4569, -101.4015)
  line L25 (61.9037, -2.2015) -> (67.4569, -2.2015)
  line L26 (65.3871, -38.0015) -> (59.6949, -38.0015)
  circle C1 centre (64.4569, -5.2015) radius 1.25
  circle C2 centre (-14.633, -29.5015) radius 1.25
  circle C3 centre (13.7417, -35.0015) radius 1.25
  circle C4 centre (-14.633, -5.7015) radius 1.25
  circle C5 centre (64.4569, -5.2015) radius 1.25
  circle C6 centre (64.536, -35.0015) radius 1.25
  circle C7 centre (64.536, -35.0015) radius 3
  concentric C6 C7
  tangent L1 C7
  dimension "d835" diameter C6 = 2.5
  dimension "d836" diameter C7 = 6
extrude "Extrude177" cut sketch "Sketch147" profile of C6 against normal blind 10
sketch "Sketch148" plane through (4.0784, 0, 15.294) normal (0.2577, 0, 0.9662) x axis (0.9662, 0, -0.2577)
  line L1 (107.867, -38.0015) -> (10.7417, -38.0015)
  line L2 (107.867, -2.2015) -> (107.867, -38.0015)
  line L3 (-18.133, -2.2015) -> (107.867, -2.2015)
  line L4 (-18.133, -33.0015) -> (-18.133, -2.2015)
  line L5 (10.7417, -33.0015) -> (-18.133, -33.0015)
  line L6 (10.7417, -38.0015) -> (10.7417, -33.0015)
  line L7 (61.9037, -4.2015) -> (61.9037, -2.2015)
  line L8 (59.6949, -4.2015) -> (61.9037, -4.2015)
  line L9 (59.6949, -8.2015) -> (59.6949, -4.2015)
  line L10 (65.3871, -8.2015) -> (59.6949, -8.2015)
  line L11 (65.3871, -32.0015) -> (65.3871, -8.2015)
  line L12 (59.6949, -32.0015) -> (65.3871, -32.0015)
  line L13 (59.6949, -38.0015) -> (59.6949, -32.0015)
  line L14 (65.3871, -38.0015) -> (59.6949, -38.0015)
  line L15 (65.3871, -95.4015) -> (65.3871, -38.0015)
  line L16 (59.6949, -95.4015) -> (65.3871, -95.4015)
  line L17 (59.6949, -99.4015) -> (59.6949, -95.4015)
  line L18 (21.6089, -99.4015) -> (59.6949, -99.4015)
  line L19 (21.6089, -95.4015) -> (21.6089, -99.4015)
  line L20 (15.3992, -95.4015) -> (21.6089, -95.4015)
  line L21 (15.3992, -90.8015) -> (15.3992, -95.4015)
  line L22 (2.3072, -90.8015) -> (15.3992, -90.8015)
  line L23 (2.3072, -101.4015) -> (2.3072, -90.8015)
  line L24 (67.4569, -101.4015) -> (2.3072, -101.4015)
  line L25 (67.4569, -2.2015) -> (67.4569, -101.4015)
  line L26 (61.9037, -2.2015) -> (67.4569, -2.2015)
  circle C1 centre (64.4569, -5.2015) radius 1.25
  circle C2 centre (-14.633, -29.5015) radius 1.25
  circle C3 centre (13.7417, -35.0015) radius 1.25
  circle C4 centre (-14.633, -5.7015) radius 1.25
  circle C5 centre (64.536, -35.0015) radius 1.25
  circle C6 centre (64.4569, -5.2015) radius 1.25
  circle C7 centre (64.536, -35.0015) radius 1.6
  circle C8 centre (64.4569, -5.2015) radius 1.6
  circle C9 centre (13.7417, -35.0015) radius 1.6
  circle C10 centre (-14.633, -29.5015) radius 1.6
  circle C11 centre (-14.633, -5.7015) radius 1.6
  concentric C5 C7
  concentric C6 C8
  concentric C3 C9
  concentric C2 C10
  concentric C4 C11
  dimension "d839" diameter C7 = 3.2
  dimension "d840" diameter C8 = 3.2
  dimension "d841" diameter C9 = 3.2
  dimension "d842" diameter C10 = 3.2
  dimension "d843" diameter C11 = 3.2
extrude "Extrude15" cut sketch "Sketch148" profile of C1 C2 C3 C4 C5 C6 C7 C8 C9 C10 C11 against normal blind 1
sketch "Sketch150" plane through (0, -62.3015, 0) normal (0, 1, 0) x axis (-1, 0, 0)
  line L1 (-61.5, -1.0533) -> (-67, -2.52)
  line L2 (-61.5, -11.0004) -> (-61.5, -1.0533)
  line L3 (-67, -11.0004) -> (-61.5, -11.0004)
  line L4 (-67, -2.52) -> (-67, -11.0004)
  circle C1 centre (-7.95, 12.8) radius 1
  arc A1 centre (-1.95, 12.8) radius 2.75 clockwise from (-2.825, 15.4071) to (-2.825, 10.1929)
  arc A2 centre (-7.95, 12.8) radius 5.75 clockwise from (-2.825, 10.1929) to (-2.825, 15.4071)
extrude "Extrude180" add sketch "Sketch150" profile of L1 L2 L3 L4 against normal blind 9.3 and against normal blind 3.3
